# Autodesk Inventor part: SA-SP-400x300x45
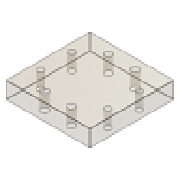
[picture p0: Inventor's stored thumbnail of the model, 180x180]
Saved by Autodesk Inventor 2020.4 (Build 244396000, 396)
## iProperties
Created: 2019-01
Part Number: SA-SP-400x300x45
Material: S 55 C
Description: Support Plate
Document SubType Name: Modeling
Designer: mel
Standard Revision: 1
Manufacturer: FUTABA
Language: fr-FR
Size Designation: 400x300x45
Categories: <MemberInstance><Categories><Category DisplayName="Moule" InternalName="349578f2-f4d4-4954-8c09-8e99297a61c0" Mnemonic="MOLD"><Category DisplayName="Plaque de m
Density: 7.85 g/cm^3
Appearance: Polycarbonate - Smoked
IsCustomPart: 1
Author: mel
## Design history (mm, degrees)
sketch "Sketch1"
  geometry: L1 (-150, 200)-(150, 200); L2 (150, 200)-(150, -200); L3 (150, -200)-(-150, -200); L4 (-150, -200)-(-150, 200); 5 further points
  constraints: 8 end point, 2 midpoint, 2 parallel, 1 horizontal, 1 horizontal alignment, 1 perpendicular, 1 vertical alignment
  dimensions: "d68" = 300 distance between parallel lines of L2 L4 (= W_); "d69" = 400 distance between parallel lines of L3 L1 (= L); "d70" = 170 vertical distance of point (0, 0) point (-67, 170) (= 0.5 x RP_L); "d71" = 67 horizontal distance of point (0, 0) point (-67, 170) (= 0.5 x RP_W); "d72" = 119 vertical distance of point (0, 0) point (-120, 119) (= 0.5 x S1_L); "d73" = 120 horizontal distance of point (0, 0) point (-120, 119) (= 0.5 x S1_W)
extrude "Extrusion1" new body sketch "Sketch1" distance "d20" = 45 (= H_); taper "d30" = 0 deg
hole "Hole1" sketch "Sketch1" diameter "d74" = 16 (= S1_d1); stored, may be unused: countersink angle "d78" = 90 deg, drill point angle "d80" = 0 deg; dims "d75" = 6, "d76" = 4, "d77" = 2, "d79" = 45 (= H_)
pattern_linear "Rectangular Pattern1" dims "d102" = 119 (computed from S1_L, Ns), "d105" = 240 (computed from S1_W, Nw)
hole "Hole2" sketch "Sketch1" diameter "d81" = 21 (= RP_d1); stored, may be unused: countersink angle "d85" = 90 deg, drill point angle "d87" = 0 deg; dims "d82" = 6, "d83" = 4, "d84" = 2, "d86" = 45 (= H_)
pattern_linear "Rectangular Pattern2" dims "d108" = 340 (computed from RP_L, Nl), "d111" = 134 (computed from RP_W, Nw)
chamfer "Chamfer1" distance "d112" = 0.5; stored, may be unused: second distance "d113" = 2, angle "d114" = 45 deg
body "Solid1"
other parameters: "L" = 400 [user parameter; used in 1 equation term], "W_" = 300 [user parameter; used in 1 equation term], "H_" = 45 [user parameter; used in 3 equation terms], "RP_W" = 134 [user parameter; used in 2 equation terms], "S1_d1" = 16 [user parameter; used in 1 equation term], "RP_d1" = 21 [user parameter; used in 1 equation term], "S1_L" = 238 [user parameter; used in 2 equation terms]
